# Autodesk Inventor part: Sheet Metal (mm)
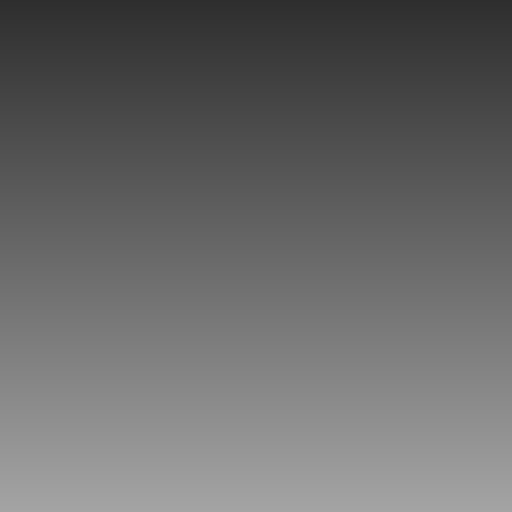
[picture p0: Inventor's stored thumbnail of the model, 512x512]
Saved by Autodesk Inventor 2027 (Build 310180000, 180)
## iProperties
Shininess: 64.0
Length Units: 11269
Angle Units: 11279
Time Units: 11290
Mass Units: 11283
Length Display Precision: 3
Angle Display Precision: 2
Compacted: True
Part Number: Sheet Metal (mm)
Document SubType Name: Sheet Metal
Created: 2002-07
Material: Generic
Density: 1 g/cm^3
Sheet Metal Rule: Default_mm
Appearance: Default
Density: 0.0
Volumn: 0.0
Area: 0.0
PropertySet Name: Model Information
Control State: 0
Master: False
Checked Out: False
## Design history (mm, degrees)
other parameters: "Thickness" = 0.5, "BendRadius" = 0.5 (= Thickness), "BendReliefWidth" = 0.5 (= Thickness), "BendReliefDepth" = 0.25 (= 0.5 x Thickness), "CornerReliefSize" = 2 (= 4 x Thickness), "SeamGap" = 0.01, "MinimumRemnant" = 1 (= 2 x Thickness), "TransitionRadius" = 0.5 (= BendRadius), "JacobiRadiusSize" = 0.5 (= BendRadius), "GapSize" = 0.5 (= Thickness)
